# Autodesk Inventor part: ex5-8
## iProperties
Shininess: 64.0
Length Units: 11272
Angle Units: 11279
Time Units: 11290
Mass Units: 11286
Length Display Precision: 3
Angle Display Precision: 2
Compacted: True
Part Number: ex5-8
Document SubType Name: Modeling
Created: 2003-11
Designer: Elise Moss
Cost Center: 0.1 lbmass
Authority: 1.87 in^3
Manufacturer: Standard
Standards Organization: Custom
Density: 0.0
Volumn: 0.0
Area: 0.0
PropertySet Name: Model Information
Control State: 0
Master: False
Checked Out: False
SaveDate: 2003-11-14
SaveTime: 18:14
TotalMass: 0.1 lbmass
TotalVolume: 1.87 in^3
Author: Elise Moss
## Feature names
1. Loft1
2. Shell1
3. Extrusion1
4. Sweep1
